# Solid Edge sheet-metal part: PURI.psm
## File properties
Author: ke06
Template: Normal.psm
Last saved by: Andris
Revision: 6
Application: Solid Edge
Accuracy: 0,990
Material Thickness: 5,00 mm
Bend Radius: 1,00 mm
Relief Width: 1,00 mm
Relief Length: 0,00 mm
Neutral Factor: 0,330
Minimum Arc Length: 0,10 mm
Deviational Tolerance: 0,10 mm
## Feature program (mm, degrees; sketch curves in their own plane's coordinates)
base tab "unnamed BaseTab 1"
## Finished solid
Body 1: solid body, 5 faces, 9 edges, 6 vertices.
  Faces by surface: plane 5
  Edges by curve: line 9
Bounding box of the edges (mm): 145.000 x 5.000 x 272.000, from (0, 0, 0) to (145, 5, 272).
Planar faces by outward normal: +y 1, -x 1, -y 1, -z 1, oblique 1
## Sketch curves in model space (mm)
line (0, 0, 272) -> (145, 0, 0)
line (0, 0, 0) -> (0, 0, 272)
line (0, 0, 0) -> (145, 0, 0)
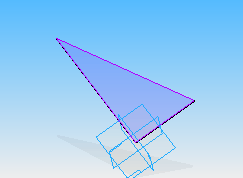
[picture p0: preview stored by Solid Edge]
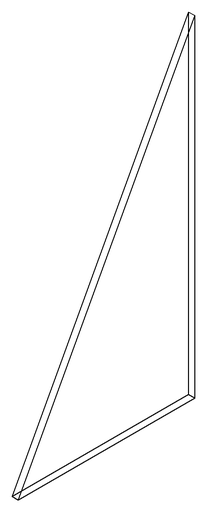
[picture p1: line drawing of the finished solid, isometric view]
